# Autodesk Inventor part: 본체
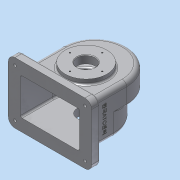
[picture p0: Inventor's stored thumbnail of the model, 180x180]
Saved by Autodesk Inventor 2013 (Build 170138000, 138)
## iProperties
Created: 2017-11
Part Number: 본체
Material: 알루미늄 6061
Document SubType Name: Modeling
Designer: Administrator
Density: 2.71 g/cm^3
Mass: 1079.49 g
Surface Area: 1182.07 cm^2
Volume: 398.335 cm^3
Author: Administrator
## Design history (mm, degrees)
sketch "스케치1"
  geometry: L1 (-58, 0)-(-58, -80); L2 (-58, -80)-(58, -80); L3 (58, 0)-(58, -80); A1 r 58 centre (0, 0) between (58, 0) and (-58, 0); 1 further point
  constraints: 6 end point, 2 perpendicular, 2 point on circle, 2 tangent, 1 centre point, 1 coincident, 1 vertical
  dimensions: "d0" = 116 diameter of A1; "d2" = 80 distance from line of L3.start L2
extrude "돌출1" new body sketch "스케치1" distance "d3" = 38; taper "d4" = 0 deg
sketch "스케치2"
  geometry: L1 (-58, -80)-(58, -80) reference; L2 (58, -80)-(58, 0) reference; L3 (-58, -23)-(-58, -80); L4 (-58, -80)-(58, -80); L5 (58, -23)-(58, -80); A1 r 58 centre (0, 0) between (58, 0) and (-58, 0) reference; A2 r 58 centre (0, -23) between (58, -23) and (-58, -23); 2 further points
  constraints: 6 end point, 2 midpoint, 2 perpendicular, 2 point on circle, 2 tangent, 1 centre point, 1 coincident, 1 parallel, 1 vertical alignment
  dimensions: "d6" = 57 distance from line of L4 L5.start; "d8" = 58 radius of A2
extrude "돌출2" join sketch "스케치2" distance "d9" = 38; taper "d10" = 0 deg
feature "쉘1" dims "d11" = 5
sketch "스케치3"
  geometry: L1 (-58, -80)-(58, -80) reference; C1 r 37.5 at (0, -15); A1 r 58 centre (0, 0) between (58, 0) and (-58, 0) reference
  constraints: 1 centre point, 1 vertical alignment
  dimensions: "d12" = 75 diameter of C1; "d13" = 65 distance from line of L1 C1.centre
extrude "돌출3" join sketch "스케치3" distance "d14" = 9; taper "d15" = 0 deg
sketch "스케치4"
  geometry: L1 (-58, -80)-(58, -80) reference; C1 r 31 at (0, -15); 1 further point
  constraints: 1 centre point, 1 vertical alignment
  dimensions: "d16" = 62 diameter of C1; "d17" = 65 distance from line of L1 C1.centre
extrude "돌출4" join sketch "스케치4" distance "d18" = 10; taper "d19" = 0 deg
sketch "스케치5"
  geometry: C1 r 31 at (0, 0) reference; 1 further point
hole "구멍1" sketch "스케치5" at (0, 0) diameter "d20" = 32; stored, may be unused: countersink angle "d24" = 90 deg, drill point angle "d26" = 118 deg; dims "d21" = 6, "d22" = 4, "d23" = 2, "d25" = 8
chamfer "모따기1" distance "d29" = 1; stored, may be unused: second distance "d30" = 2, angle "d31" = 45 deg
fillet "모깎기2" dims "d32" = 3
fillet "모깎기3" dims "d33" = 3
node "작업 평면1"
sketch "스케치6"
  geometry: L1 (58, 38)-(-58, 38) reference; C1 r 6 at (0, 19); 1 further point
  constraints: 1 centre point, 1 vertical alignment
  dimensions: "d35" = 12 diameter of C1; "d47" = 19 distance from line of L1 C1.centre
extrude "돌출5" join sketch "스케치6" stored distance "d38" = 10; taper "d39" = 0 deg
sketch "스케치7"
  geometry: C1 r 6 at (0, 0) reference; 1 further point
hole "구멍2" sketch "스케치7" at (0, 0) diameter "d40" = 4.459; stored, may be unused: countersink angle "d44" = 90 deg, drill point angle "d46" = 118 deg; dims "d41" = 6, "d42" = 4, "d43" = 2, "d45" = 8
sketch "스케치8"
  geometry: L1 (116, 0)-(116, -76) reference; L2 (0, 0)-(116, 0) reference; L3 (0, 0)-(0, -76) reference; L4 (116, -76)-(0, -76) reference; L5 (-17, 17)-(133, 17); L6 (133, 17)-(133, -93); L7 (133, -93)-(-17, -93); L8 (-17, -93)-(-17, 17); 3 further points
  constraints: 8 end point, 2 midpoint, 2 parallel, 1 horizontal, 1 horizontal alignment, 1 perpendicular, 1 vertical alignment
  dimensions: "d48" = 110 distance of L5.end L6.end; "d50" = 150 distance of L6.end L7.end
extrude "돌출6" join sketch "스케치8" distance "d51" = 15; taper "d52" = 0 deg
fillet "모깎기4" dims "d53" = 12
sketch "스케치9"
  geometry: A1 r 12 centre (-5, 81) between (-5, 93) and (-17, 81) reference; 1 further point
hole "구멍3" sketch "스케치9" at (-5, 81) diameter "d54" = 5; stored, may be unused: countersink angle "d58" = 90 deg, drill point angle "d60" = 0 deg; dims "d55" = 6, "d56" = 12, "d57" = 5, "d59" = 8
sketch "스케치10"
  geometry: A1 r 12 centre (-5, -5) between (-17, -5) and (-5, -17) reference; A2 r 12 centre (121, -5) between (121, -17) and (133, -5) reference; A3 r 12 centre (121, 81) between (133, 81) and (121, 93) reference; 1 further point
hole "구멍4" sketch "스케치10" at (-5, -5), (121, -5), (121, 81) diameter "d61" = 5; stored, may be unused: countersink angle "d65" = 90 deg, drill point angle "d67" = 0 deg; dims "d62" = 6, "d63" = 12, "d64" = 5, "d66" = 8
sketch "스케치11"
  geometry: C1 r 31 at (0, 0) reference; 2 further points
  constraints: 1 vertical alignment
  dimensions: "d68" = 26 distance of C1.centre point (0, 26)
hole "구멍5" sketch "스케치11" at (0, 26) diameter "d69" = 2.459; stored, may be unused: countersink angle "d73" = 90 deg, drill point angle "d75" = 118 deg; dims "d70" = 6, "d71" = 12, "d72" = 5, "d74" = 8
sketch "스케치12"
  geometry: C1 r 37.5 at (0, 0) reference; 2 further points
  constraints: 1 vertical alignment
  dimensions: "d79" = 29 distance of C1.centre point (0, 29)
hole "구멍6" sketch "스케치12" at (0, 29) diameter "d80" = 2.459; stored, may be unused: countersink angle "d84" = 90 deg, drill point angle "d86" = 118 deg; dims "d81" = 6, "d82" = 12, "d83" = 5, "d85" = 8
fillet "모깎기6" dims "d91" = 8
fillet "모깎기7" dims "d92" = 3
fillet "모깎기8" dims "d93" = 3
sketch "스케치13"
  geometry: L1 (-13, -80)-(-25, -80) reference; L2 (-8, 0)-(-8, -62) reference; 2 further points
  constraints: 1 other
  dimensions: "d94" = 40 distance from line of L1 point (30, -40); "d95" = 38 distance from line of L2 point (30, -40)
feature "엠보싱1" sketch "스케치13" dims "d96" = 0.5, "d97" = 0
node "솔리드1"
pattern_circular "원형 패턴1" dims angle "d77" = 360 deg
pattern_circular "원형 패턴2" dims angle "d88" = 360 deg
other parameters: "d5" = 116, "d34" = 64
